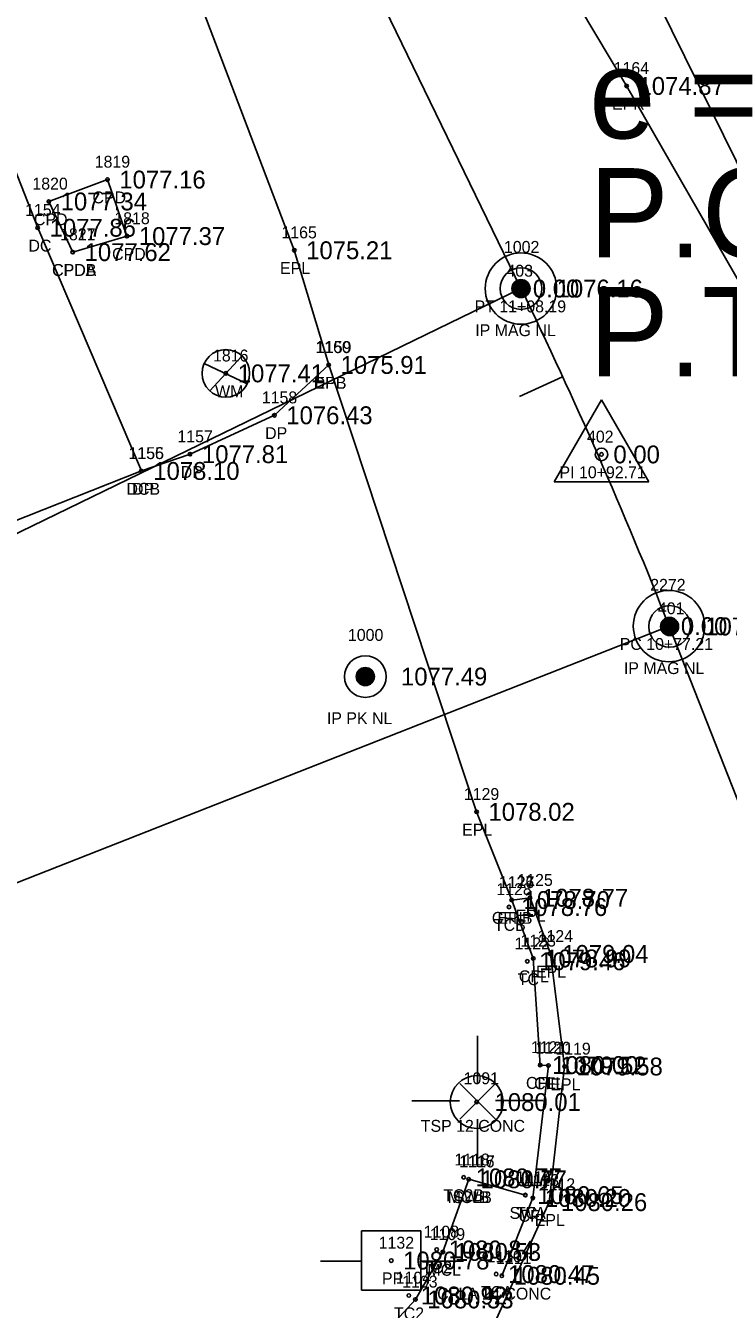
# Model space of a CAD drawing. Extents: x 1578957 to 1581675, y 1115963 to 1120391.
# Drawn here: x 1580400.6 to 1580459.7, y 1116454.6 to 1116562.5 of the extents above; entities that cross this region are included whole.
import ezdxf

# ---------------------------------------------------------------- set-up
doc = ezdxf.new("R2010")
doc.units = 0
for name, color, linetype in [('RD_EX_Conc', 7, 'Continuous'), ('RD_EX_Conc_txCode', 7, 'Continuous'), ('RD_EX_DR_Pipe', 7, 'Continuous'), ('RD_EX_Driveway', 7, 'Continuous'), ('RD_EX_Driveway_txCode', 7, 'Continuous'), ('RD_EX_DV_Prop_txCode', 7, 'Continuous'), ('RD_EX_DV_PropPin', 7, 'Continuous'), ('RD_EX_Road', 7, 'Continuous'), ('RD_EX_Road_txCode', 7, 'Continuous'), ('RD_EX_SU_Pole', 7, 'Continuous'), ('RD_EX_TX_Conc_ELEV', 7, 'Continuous'), ('RD_EX_TX_Driveway_ELEV', 7, 'Continuous'), ('RD_EX_TX_DV_Prop_ELEV', 7, 'Continuous'), ('RD_EX_TX_Road_ELEV', 7, 'Continuous'), ('RD_EX_TX_UT_ELEV', 7, 'Continuous'), ('RD_EX_UT', 7, 'Continuous'), ('RD_EX_UT_txCode', 7, 'Continuous'), ('RD_HC_Cl', 7, 'Continuous'), ('RD_HC_Data', 7, 'Continuous'), ('RD_HC_Data_Tic', 7, 'Continuous'), ('RD_HC_Survey_ELEV', 7, 'Continuous'), ('RD_HC_txCode', 7, 'Continuous'), ('RD_SMD_Locator', 7, 'Continuous')]:
    doc.layers.add(name, color=color, linetype=linetype)

msp = doc.modelspace()

# ---------------------------------------------------------------- linework, layer by layer
at = {"layer": 'RD_EX_Conc'}
msp.add_line((1580442.64, 1116464.19), (1580437.88, 1116465.52), dxfattribs=at)
for points in [[(1580387.19, 1116579.23), (1580392.87, 1116567.87), (1580401.66, 1116545.49), (1580410.37, 1116525.05)], [(1580404.6, 1116543.44), (1580409.16, 1116544.79), (1580407.52, 1116549.54), (1580402.59, 1116547.7), (1580404.6, 1116543.44)], [(1580440.66, 1116457.41), (1580443.27, 1116463.95), (1580444.58, 1116475.08), (1580443.89, 1116475.12), (1580443.3, 1116484.08), (1580441.49, 1116488.99)], [(1580428.03, 1116449.59), (1580433.4, 1116455.42), (1580435.71, 1116459.41), (1580437.88, 1116465.52)]]:
    msp.add_lwpolyline(points, dxfattribs=at)
at = {"layer": 'RD_EX_DR_Pipe'}
msp.add_lwpolyline([(1580531.38, 1116486.91), (1580479.87, 1116511.57), (1580444.12, 1116584.07)], dxfattribs=at)
at = {"layer": 'RD_EX_Driveway'}
msp.add_lwpolyline([(1580390.43, 1116465.58), (1580390.91, 1116467.26), (1580378.07, 1116512.9), (1580392.44, 1116517.96), (1580410.37, 1116525.05), (1580414.46, 1116526.46), (1580421.55, 1116529.73), (1580426.11, 1116533.96)], dxfattribs=at)
at = {"layer": 'RD_EX_DV_PropPin'}
for p, q in [((1580442.06, 1116539.65), (1580442.06, 1116541.11)), ((1580442.09, 1116539.64), (1580442.09, 1116541.12)), ((1580442.13, 1116539.63), (1580442.13, 1116541.13)), ((1580442.16, 1116539.62), (1580442.16, 1116541.13)), ((1580442.2, 1116539.62), (1580442.2, 1116541.14)), ((1580442.23, 1116539.62), (1580442.23, 1116541.14)), ((1580442.27, 1116539.62), (1580442.27, 1116541.14)), ((1580442.3, 1116539.62), (1580442.3, 1116541.14)), ((1580442.34, 1116539.62), (1580442.34, 1116541.14)), ((1580442.37, 1116539.62), (1580442.37, 1116541.13)), ((1580442.41, 1116539.63), (1580442.41, 1116541.13)), ((1580442.44, 1116539.64), (1580442.44, 1116541.12)), ((1580442.48, 1116539.65), (1580442.48, 1116541.11)), ((1580441.53, 1116540.18), (1580441.53, 1116540.57)), ((1580441.57, 1116540.08), (1580441.57, 1116540.68)), ((1580441.6, 1116540.01), (1580441.6, 1116540.75)), ((1580441.64, 1116539.95), (1580441.64, 1116540.8)), ((1580441.67, 1116539.9), (1580441.67, 1116540.85)), ((1580441.71, 1116539.86), (1580441.71, 1116540.89)), ((1580441.74, 1116539.83), (1580441.74, 1116540.93)), ((1580441.78, 1116539.8), (1580441.78, 1116540.96)), ((1580441.81, 1116539.77), (1580441.81, 1116540.99)), ((1580441.85, 1116539.74), (1580441.85, 1116541.01)), ((1580441.88, 1116539.72), (1580441.88, 1116541.03)), ((1580441.92, 1116539.7), (1580441.92, 1116541.05)), ((1580441.95, 1116539.68), (1580441.95, 1116541.07)), ((1580441.99, 1116539.67), (1580441.99, 1116541.08)), ((1580442.02, 1116539.66), (1580442.02, 1116541.1)), ((1580442.51, 1116539.66), (1580442.51, 1116541.1)), ((1580442.55, 1116539.67), (1580442.55, 1116541.08)), ((1580442.58, 1116539.68), (1580442.58, 1116541.07)), ((1580442.62, 1116539.7), (1580442.62, 1116541.05)), ((1580442.65, 1116539.72), (1580442.65, 1116541.03)), ((1580442.69, 1116539.74), (1580442.69, 1116541.01)), ((1580442.72, 1116539.77), (1580442.72, 1116540.99)), ((1580442.76, 1116539.8), (1580442.76, 1116540.96)), ((1580442.79, 1116539.83), (1580442.79, 1116540.93)), ((1580442.83, 1116539.86), (1580442.83, 1116540.89)), ((1580442.86, 1116539.9), (1580442.86, 1116540.85)), ((1580442.9, 1116539.95), (1580442.9, 1116540.8)), ((1580442.93, 1116540.01), (1580442.93, 1116540.75)), ((1580442.97, 1116540.08), (1580442.97, 1116540.68)), ((1580443, 1116540.18), (1580443, 1116540.57)), ((1580454.02, 1116511.78), (1580454.02, 1116512.18)), ((1580454.06, 1116511.68), (1580454.06, 1116512.28)), ((1580454.09, 1116511.61), (1580454.09, 1116512.35)), ((1580454.13, 1116511.55), (1580454.13, 1116512.41)), ((1580454.16, 1116511.5), (1580454.16, 1116512.45)), ((1580454.2, 1116511.46), (1580454.2, 1116512.49)), ((1580454.23, 1116511.43), (1580454.23, 1116512.53)), ((1580454.27, 1116511.4), (1580454.27, 1116512.56)), ((1580454.3, 1116511.37), (1580454.3, 1116512.59)), ((1580454.34, 1116511.34), (1580454.34, 1116512.61)), ((1580454.37, 1116511.32), (1580454.37, 1116512.64)), ((1580454.41, 1116511.3), (1580454.41, 1116512.65)), ((1580454.44, 1116511.29), (1580454.44, 1116512.67)), ((1580454.48, 1116511.27), (1580454.48, 1116512.69)), ((1580454.51, 1116511.26), (1580454.51, 1116512.7)), ((1580454.55, 1116511.25), (1580454.55, 1116512.71)), ((1580454.58, 1116511.24), (1580454.58, 1116512.72)), ((1580454.62, 1116511.23), (1580454.62, 1116512.73)), ((1580454.65, 1116511.23), (1580454.65, 1116512.73)), ((1580454.69, 1116511.22), (1580454.69, 1116512.74)), ((1580454.72, 1116511.22), (1580454.72, 1116512.74)), ((1580454.76, 1116511.22), (1580454.76, 1116512.74)), ((1580454.79, 1116511.22), (1580454.79, 1116512.74)), ((1580454.83, 1116511.22), (1580454.83, 1116512.74)), ((1580454.86, 1116511.23), (1580454.86, 1116512.73)), ((1580454.9, 1116511.23), (1580454.9, 1116512.73)), ((1580454.93, 1116511.24), (1580454.93, 1116512.72)), ((1580454.97, 1116511.25), (1580454.97, 1116512.71)), ((1580455, 1116511.26), (1580455, 1116512.7)), ((1580455.04, 1116511.27), (1580455.04, 1116512.69)), ((1580455.07, 1116511.29), (1580455.07, 1116512.67)), ((1580455.11, 1116511.3), (1580455.11, 1116512.65)), ((1580455.14, 1116511.32), (1580455.14, 1116512.64)), ((1580455.18, 1116511.34), (1580455.18, 1116512.61)), ((1580455.21, 1116511.37), (1580455.21, 1116512.59)), ((1580455.25, 1116511.4), (1580455.25, 1116512.56)), ((1580455.28, 1116511.43), (1580455.28, 1116512.53)), ((1580455.32, 1116511.46), (1580455.32, 1116512.49)), ((1580455.35, 1116511.5), (1580455.35, 1116512.45)), ((1580455.39, 1116511.55), (1580455.39, 1116512.41)), ((1580455.42, 1116511.61), (1580455.42, 1116512.35)), ((1580455.46, 1116511.68), (1580455.46, 1116512.28)), ((1580455.49, 1116511.78), (1580455.49, 1116512.18)), ((1580428.46, 1116507.57), (1580428.46, 1116507.97)), ((1580428.49, 1116507.47), (1580428.49, 1116508.07)), ((1580428.53, 1116507.4), (1580428.53, 1116508.14)), ((1580428.56, 1116507.34), (1580428.56, 1116508.2)), ((1580428.6, 1116507.3), (1580428.6, 1116508.24)), ((1580428.63, 1116507.25), (1580428.63, 1116508.28)), ((1580428.67, 1116507.22), (1580428.67, 1116508.32)), ((1580428.7, 1116507.19), (1580428.7, 1116508.35)), ((1580428.74, 1116507.16), (1580428.74, 1116508.38)), ((1580428.77, 1116507.13), (1580428.77, 1116508.4)), ((1580428.81, 1116507.11), (1580428.81, 1116508.43)), ((1580428.84, 1116507.09), (1580428.84, 1116508.45)), ((1580428.88, 1116507.08), (1580428.88, 1116508.46)), ((1580428.91, 1116507.06), (1580428.91, 1116508.48)), ((1580428.95, 1116507.05), (1580428.95, 1116508.49)), ((1580428.98, 1116507.04), (1580428.98, 1116508.5)), ((1580429.02, 1116507.03), (1580429.02, 1116508.51)), ((1580429.05, 1116507.02), (1580429.05, 1116508.52)), ((1580429.09, 1116507.02), (1580429.09, 1116508.52)), ((1580429.12, 1116507.01), (1580429.12, 1116508.53)), ((1580429.16, 1116507.01), (1580429.16, 1116508.53)), ((1580429.19, 1116507.01), (1580429.19, 1116508.53)), ((1580429.23, 1116507.01), (1580429.23, 1116508.53)), ((1580429.26, 1116507.01), (1580429.26, 1116508.53)), ((1580429.3, 1116507.02), (1580429.3, 1116508.52)), ((1580429.33, 1116507.02), (1580429.33, 1116508.52)), ((1580429.37, 1116507.03), (1580429.37, 1116508.51)), ((1580429.4, 1116507.04), (1580429.4, 1116508.5)), ((1580429.44, 1116507.05), (1580429.44, 1116508.49)), ((1580429.47, 1116507.06), (1580429.47, 1116508.48)), ((1580429.51, 1116507.08), (1580429.51, 1116508.46)), ((1580429.54, 1116507.09), (1580429.54, 1116508.45)), ((1580429.58, 1116507.11), (1580429.58, 1116508.43)), ((1580429.61, 1116507.13), (1580429.61, 1116508.4)), ((1580429.65, 1116507.16), (1580429.65, 1116508.38)), ((1580429.68, 1116507.19), (1580429.68, 1116508.35)), ((1580429.72, 1116507.22), (1580429.72, 1116508.32)), ((1580429.75, 1116507.25), (1580429.75, 1116508.28)), ((1580429.79, 1116507.3), (1580429.79, 1116508.24)), ((1580429.82, 1116507.34), (1580429.82, 1116508.2)), ((1580429.86, 1116507.4), (1580429.86, 1116508.14)), ((1580429.89, 1116507.47), (1580429.89, 1116508.07)), ((1580429.93, 1116507.57), (1580429.93, 1116507.97))]:
    msp.add_line(p, q, dxfattribs=at)
for centre, radius in [((1580442.27, 1116540.38), 1.75), ((1580442.27, 1116540.38), 0.761), ((1580454.76, 1116511.98), 1.75), ((1580454.76, 1116511.98), 0.761), ((1580429.19, 1116507.77), 1.75), ((1580429.19, 1116507.77), 0.761)]:
    msp.add_circle(centre, radius, dxfattribs=at)
at = {"layer": 'RD_EX_Road'}
for points in [[(1580570.71, 1116498.67), (1580529.36, 1116480.65), (1580519.91, 1116479.43), (1580510.64, 1116479.83), (1580504.14, 1116481.67), (1580497.17, 1116485.13), (1580490.27, 1116490.58), (1580483.83, 1116498.29), (1580485.04, 1116499.02), (1580478.37, 1116510.01), (1580451.15, 1116557.41), (1580425.99, 1116599.55), (1580403.29, 1116644.83), (1580382.32, 1116688.41), (1580373.95, 1116705.15), (1580352.79, 1116744.5), (1580332.46, 1116780.72), (1580308.51, 1116820.53), (1580282.29, 1116862.52), (1580254.51, 1116905.2), (1580227.5, 1116946.75), (1580201.69, 1116988.26)], [(1580373.02, 1116418.01), (1580425.37, 1116439.24), (1580432.48, 1116444.21), (1580439.18, 1116451.49), (1580444.63, 1116463.6), (1580445.94, 1116475), (1580444.74, 1116484.46), (1580443.03, 1116489.18), (1580441.49, 1116488.99), (1580438.54, 1116496.4), (1580426.11, 1116533.96), (1580423.22, 1116543.6), (1580405.6, 1116590.01), (1580384.87, 1116635.19), (1580363.63, 1116679.91), (1580314.77, 1116769.46), (1580304.81, 1116786.68), (1580291.3, 1116810.33), (1580264.82, 1116852.68), (1580237.53, 1116894.27), (1580210.3, 1116936.03), (1580183.44, 1116978.21)]]:
    msp.add_lwpolyline(points, dxfattribs=at)
at = {"layer": 'RD_EX_SU_Pole'}
for p, q in [((1580438.62, 1116473.58), (1580438.62, 1116477.58)), ((1580440.12, 1116473.58), (1580437.12, 1116470.58)), ((1580437.12, 1116473.58), (1580440.12, 1116470.58)), ((1580437.1, 1116472.12), (1580433.1, 1116472.12)), ((1580440.14, 1116472.14), (1580444.15, 1116472.14)), ((1580438.62, 1116470.58), (1580438.62, 1116466.58))]:
    msp.add_line(p, q, dxfattribs=at)
msp.add_circle((1580438.55, 1116472.01), 2.22, dxfattribs=at)
at = {"layer": 'RD_EX_UT'}
for p, q in [((1580416.12, 1116531.79), (1580418.79, 1116534.68)), ((1580415.64, 1116534.08), (1580419.27, 1116532.37)), ((1580433.86, 1116461.2), (1580428.86, 1116461.2)), ((1580428.86, 1116461.2), (1580428.86, 1116456.2)), ((1580433.86, 1116456.2), (1580433.86, 1116461.2)), ((1580425.43, 1116458.64), (1580428.9, 1116458.64)), ((1580433.79, 1116458.64), (1580437.43, 1116458.64)), ((1580428.86, 1116456.2), (1580433.86, 1116456.2))]:
    msp.add_line(p, q, dxfattribs=at)
msp.add_circle((1580417.47, 1116533.25), 2, dxfattribs=at)
at = {"layer": 'RD_HC_Cl'}
for p, q in [((1580442.27, 1116540.38), (1580382.63, 1116663.15)), ((1580482.98, 1116440.16), (1580454.72, 1116512.01))]:
    msp.add_line(p, q, dxfattribs=at)
msp.add_arc((1580082.49, 1116365.6), 399.99, 21.4709, 25.9095, dxfattribs=at)
at = {"layer": 'RD_HC_Data'}
for p, q in [((1580442.27, 1116540.38), (1580338.19, 1116489.82)), ((1580445.07, 1116524.14), (1580449.04, 1116531.02)), ((1580449.04, 1116531.02), (1580453.01, 1116524.14)), ((1580445.07, 1116524.14), (1580453.01, 1116524.14)), ((1580454.72, 1116512.01), (1580346.71, 1116469.53))]:
    msp.add_line(p, q, dxfattribs=at)
for centre, radius in [((1580442.27, 1116540.38), 3), ((1580442.27, 1116540.38), 0.282), ((1580449.04, 1116526.44), 0.529), ((1580454.71, 1116512.01), 3), ((1580454.71, 1116512.01), 0.282)]:
    msp.add_circle(centre, radius, dxfattribs=at)
at = {"layer": 'RD_HC_Data_Tic'}
msp.add_line((1580445.77, 1116532.97), (1580442.14, 1116531.3), dxfattribs=at)
at = {"layer": 'RD_SMD_Locator'}
for centre in [(1580451.15, 1116557.41), (1580407.52, 1116549.54), (1580402.59, 1116547.7), (1580401.66, 1116545.49), (1580409.16, 1116544.79), (1580404.6, 1116543.44), (1580404.6, 1116543.44), (1580423.22, 1116543.6), (1580442.27, 1116540.38), (1580442.27, 1116540.38), (1580426.11, 1116533.96), (1580426.11, 1116533.96), (1580417.47, 1116533.25), (1580421.55, 1116529.73), (1580414.46, 1116526.46), (1580449.04, 1116526.44), (1580410.37, 1116525.05), (1580410.37, 1116525.05), (1580454.71, 1116512.01), (1580454.76, 1116511.98), (1580429.19, 1116507.77), (1580438.54, 1116496.4), (1580443.03, 1116489.18), (1580441.27, 1116488.4), (1580441.49, 1116488.99), (1580441.49, 1116488.99), (1580442.8, 1116483.84), (1580443.3, 1116484.08), (1580444.74, 1116484.46), (1580443.89, 1116475.12), (1580444.58, 1116475.08), (1580445.94, 1116475), (1580438.55, 1116472.01), (1580437.46, 1116465.68), (1580437.88, 1116465.52), (1580437.88, 1116465.52), (1580442.64, 1116464.19), (1580442.64, 1116464.19), (1580443.27, 1116463.95), (1580444.63, 1116463.6), (1580435.19, 1116459.62), (1580435.71, 1116459.41), (1580431.37, 1116458.69), (1580440.19, 1116457.55), (1580440.66, 1116457.41), (1580432.85, 1116455.75), (1580433.4, 1116455.42)]:
    msp.add_circle(centre, 0.15, dxfattribs=at)

# ---------------------------------------------------------------- texts
at = {"layer": 'RD_EX_Conc_txCode'}
for s, p in [('1819', (1580406.45, 1116550.54)), ('1820', (1580401.21, 1116548.7)), ('CPD', (1580406.26, 1116547.54)), ('1154', (1580400.6, 1116546.49)), ('CPD', (1580401.34, 1116545.7)), ('1818', (1580408.1, 1116545.79)), ('1817', (1580403.54, 1116544.44)), ('1821', (1580403.54, 1116544.44)), ('DC', (1580400.88, 1116543.49)), ('CPD', (1580407.91, 1116542.79)), ('CPDA', (1580402.86, 1116541.44)), ('CPDB', (1580402.88, 1116541.44)), ('1155', (1580409.3, 1116526.05)), ('DCB', (1580409.12, 1116523.05)), ('1128', (1580440.2, 1116489.4)), ('1126', (1580440.41, 1116489.99)), ('CFLB', (1580439.82, 1116486.99)), ('TCB', (1580440, 1116486.4)), ('1123', (1580442.23, 1116485.08)), ('1122', (1580441.73, 1116484.84)), ('TC', (1580442, 1116481.84)), ('CFL', (1580442.09, 1116482.08)), ('1121', (1580443.11, 1116476.12)), ('1120', (1580443.48, 1116476.08)), ('CFL', (1580442.69, 1116473.12)), ('CFL', (1580443.38, 1116473.08)), ('1118', (1580436.68, 1116466.68)), ('1116', (1580437.07, 1116466.52)), ('1117', (1580437.1, 1116466.52)), ('1114', (1580441.86, 1116465.19)), ('1115', (1580441.86, 1116465.19)), ('1113', (1580442.5, 1116464.95)), ('TC2B', (1580435.74, 1116463.68)), ('MCLB', (1580436.11, 1116463.52)), ('SWB', (1580436.56, 1116463.52)), ('SWA', (1580441.31, 1116462.19)), ('TC', (1580441.85, 1116462.19)), ('CFL', (1580442.07, 1116461.95)), ('1108', (1580434.09, 1116460.62)), ('1109', (1580434.6, 1116460.41)), ('1110', (1580439.37, 1116458.55)), ('1111', (1580440.17, 1116458.41)), ('TC2', (1580433.95, 1116457.62)), ('MCL', (1580434.41, 1116457.41)), ('1104', (1580431.74, 1116456.75)), ('1103', (1580432.29, 1116456.42)), ('CFLA 24 CONC', (1580435.23, 1116455.41)), ('TCA', (1580438.91, 1116455.55)), ('TC2', (1580431.6, 1116453.75))]:
    msp.add_text(s, height=1, dxfattribs=at).set_placement(p)
at = {"layer": 'RD_EX_Driveway_txCode'}
for s, p in [('1159', (1580425.05, 1116534.96)), ('DPB', (1580424.86, 1116531.96)), ('1158', (1580420.49, 1116530.73)), ('1157', (1580413.4, 1116527.46)), ('DP', (1580420.77, 1116527.73)), ('1156', (1580409.28, 1116526.05)), ('DP', (1580413.68, 1116524.46)), ('DP', (1580409.59, 1116523.05))]:
    msp.add_text(s, height=1, dxfattribs=at).set_placement(p)
at = {"layer": 'RD_EX_DV_Prop_txCode'}
for s, p in [('1002', (1580440.84, 1116543.38)), ('IP MAG NL', (1580438.43, 1116536.38)), ('2272', (1580453.13, 1116514.98)), ('1000', (1580427.73, 1116510.77)), ('IP MAG NL', (1580450.92, 1116507.98)), ('IP PK NL', (1580425.96, 1116503.77))]:
    msp.add_text(s, height=1, dxfattribs=at).set_placement(p)
at = {"layer": 'RD_EX_Road_txCode'}
for s, p in [('1164', (1580450.06, 1116558.41)), ('EPR', (1580449.92, 1116555.41)), ('1165', (1580422.14, 1116544.6)), ('EPL', (1580422.02, 1116541.6)), ('1160', (1580424.99, 1116534.96)), ('EPL', (1580424.91, 1116531.96)), ('1129', (1580437.47, 1116497.4)), ('EPL', (1580437.33, 1116494.4)), ('1127', (1580440.43, 1116489.99)), ('1125', (1580441.97, 1116490.18)), ('EPL', (1580440.29, 1116486.99)), ('EPL', (1580441.82, 1116487.18)), ('1124', (1580443.67, 1116485.46)), ('EPL', (1580443.53, 1116482.46)), ('1119', (1580445.16, 1116476)), ('EPL', (1580444.74, 1116473)), ('1112', (1580443.85, 1116464.6)), ('EPL', (1580443.43, 1116461.6))]:
    msp.add_text(s, height=1, dxfattribs=at).set_placement(p)
at = {"layer": 'RD_EX_TX_Conc_ELEV'}
for s, p in [('1077.16', (1580408.52, 1116548.79)), ('1077.34', (1580403.59, 1116546.95)), ('1077.86', (1580402.66, 1116544.74)), ('1077.37', (1580410.16, 1116544.04)), ('1077.62', (1580405.6, 1116542.69)), ('1077.62', (1580405.6, 1116542.69)), ('1078.10', (1580411.37, 1116524.3)), ('1078.70', (1580442.49, 1116488.24)), ('1078.76', (1580442.27, 1116487.65)), ('1079.46', (1580443.8, 1116483.09)), ('1078.99', (1580444.3, 1116483.33)), ('1080.00', (1580444.89, 1116474.37)), ('1079.52', (1580445.58, 1116474.33)), ('1080.77', (1580438.46, 1116464.93)), ('1080.77', (1580438.88, 1116464.77)), ('1080.77', (1580438.88, 1116464.77)), ('1080.65', (1580443.64, 1116463.44)), ('1080.65', (1580443.64, 1116463.44)), ('1080.20', (1580444.27, 1116463.2)), ('1080.84', (1580436.19, 1116458.87)), ('1080.53', (1580436.71, 1116458.66)), ('1080.47', (1580441.19, 1116456.8)), ('1080.45', (1580441.66, 1116456.66)), ('1080.92', (1580433.85, 1116455)), ('1080.53', (1580434.4, 1116454.67))]:
    msp.add_text(s, height=1.5, dxfattribs=at).set_placement(p)
at = {"layer": 'RD_EX_TX_Driveway_ELEV'}
for s, p in [('1075.91', (1580427.11, 1116533.21)), ('1076.43', (1580422.55, 1116528.98)), ('1077.81', (1580415.46, 1116525.71)), ('1078.10', (1580411.37, 1116524.3))]:
    msp.add_text(s, height=1.5, dxfattribs=at).set_placement(p)
at = {"layer": 'RD_EX_TX_DV_Prop_ELEV'}
for s, p in [('1076.16', (1580445.27, 1116539.63)), ('1077.98', (1580457.76, 1116511.23)), ('1077.49', (1580432.19, 1116507.02))]:
    msp.add_text(s, height=1.5, dxfattribs=at).set_placement(p)
at = {"layer": 'RD_EX_TX_Road_ELEV'}
for s, p in [('1074.87', (1580452.15, 1116556.66)), ('1075.21', (1580424.22, 1116542.85)), ('1075.91', (1580427.11, 1116533.21)), ('1078.02', (1580439.54, 1116495.65)), ('1078.70', (1580442.49, 1116488.24)), ('1078.77', (1580444.03, 1116488.43)), ('1079.04', (1580445.74, 1116483.71)), ('1079.58', (1580446.94, 1116474.25)), ('1080.26', (1580445.63, 1116462.85))]:
    msp.add_text(s, height=1.5, dxfattribs=at).set_placement(p)
at = {"layer": 'RD_EX_TX_UT_ELEV'}
for s, p in [('1077.41', (1580418.47, 1116532.5)), ('1080.01', (1580440.05, 1116471.26))]:
    msp.add_text(s, height=1.5, dxfattribs=at).set_placement(p)
at = {"layer": 'RD_EX_UT_txCode'}
for s, p in [('1816', (1580416.39, 1116534.25)), ('WM', (1580416.57, 1116531.25)), ('1091', (1580437.45, 1116473.51)), ('TSP 12 CONC', (1580433.85, 1116469.51)), ('1132', (1580430.31, 1116459.69)), ('PP', (1580430.59, 1116456.69))]:
    msp.add_text(s, height=1, dxfattribs=at).set_placement(p)
at = {"layer": 'RD_HC_Data'}
for s, p in [('e = ', (1580448, 1116553)), ('P.C. - LG% = ', (1580448, 1116543)), ('P.T. - LG% = ', (1580448, 1116533))]:
    msp.add_text(s, height=7.5, dxfattribs=at).set_placement(p)
at = {"layer": 'RD_HC_Survey_ELEV'}
for s, p in [('0.00', (1580443.27, 1116539.63)), ('0.00', (1580450.04, 1116525.69)), ('0.00', (1580455.71, 1116511.26)), ('1080.78', (1580432.37, 1116457.94))]:
    msp.add_text(s, height=1.5, dxfattribs=at).set_placement(p)
at = {"layer": 'RD_HC_txCode'}
for s, p in [('403', (1580441.05, 1116541.38)), ('PT 11+08.19', (1580438.37, 1116538.38)), ('402', (1580447.82, 1116527.44)), ('PI 10+92.71', (1580445.51, 1116524.44)), ('401', (1580453.78, 1116513.01)), ('PC 10+77.21', (1580450.57, 1116510.01))]:
    msp.add_text(s, height=1, dxfattribs=at).set_placement(p)

doc.saveas('drawing.dxf')
